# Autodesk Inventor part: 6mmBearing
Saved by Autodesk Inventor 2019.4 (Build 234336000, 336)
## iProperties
Created: 2020-02
Part Number: 6mmBearing
Material: Generic
Document SubType Name: Modeling
Designer: Administrator
Density: 1 g/cm^3
Appearance: Default
Title: 6mmBearing v2
Author: Administrator
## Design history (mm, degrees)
feature "Body1"
body "Solid1"
